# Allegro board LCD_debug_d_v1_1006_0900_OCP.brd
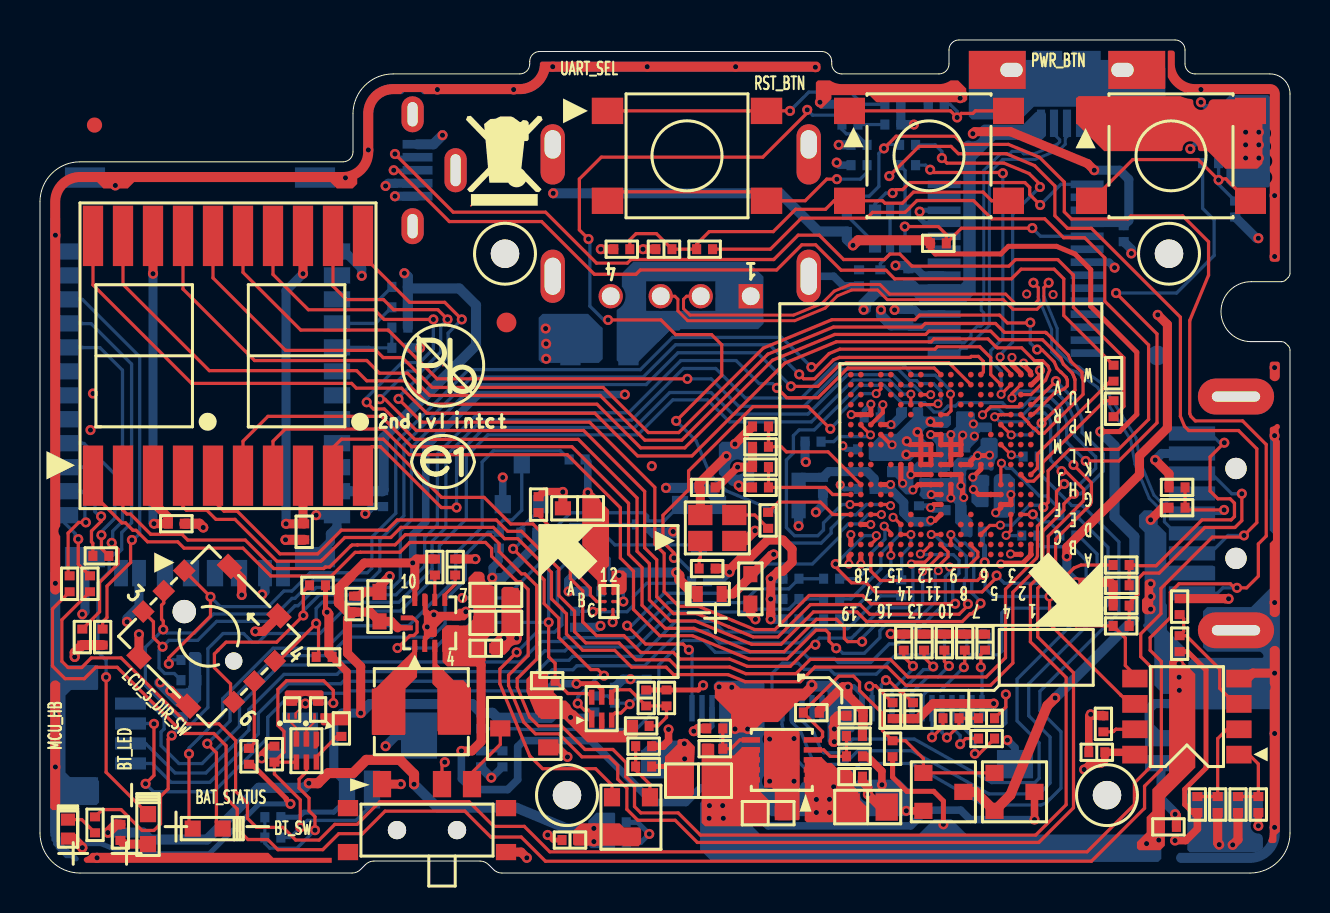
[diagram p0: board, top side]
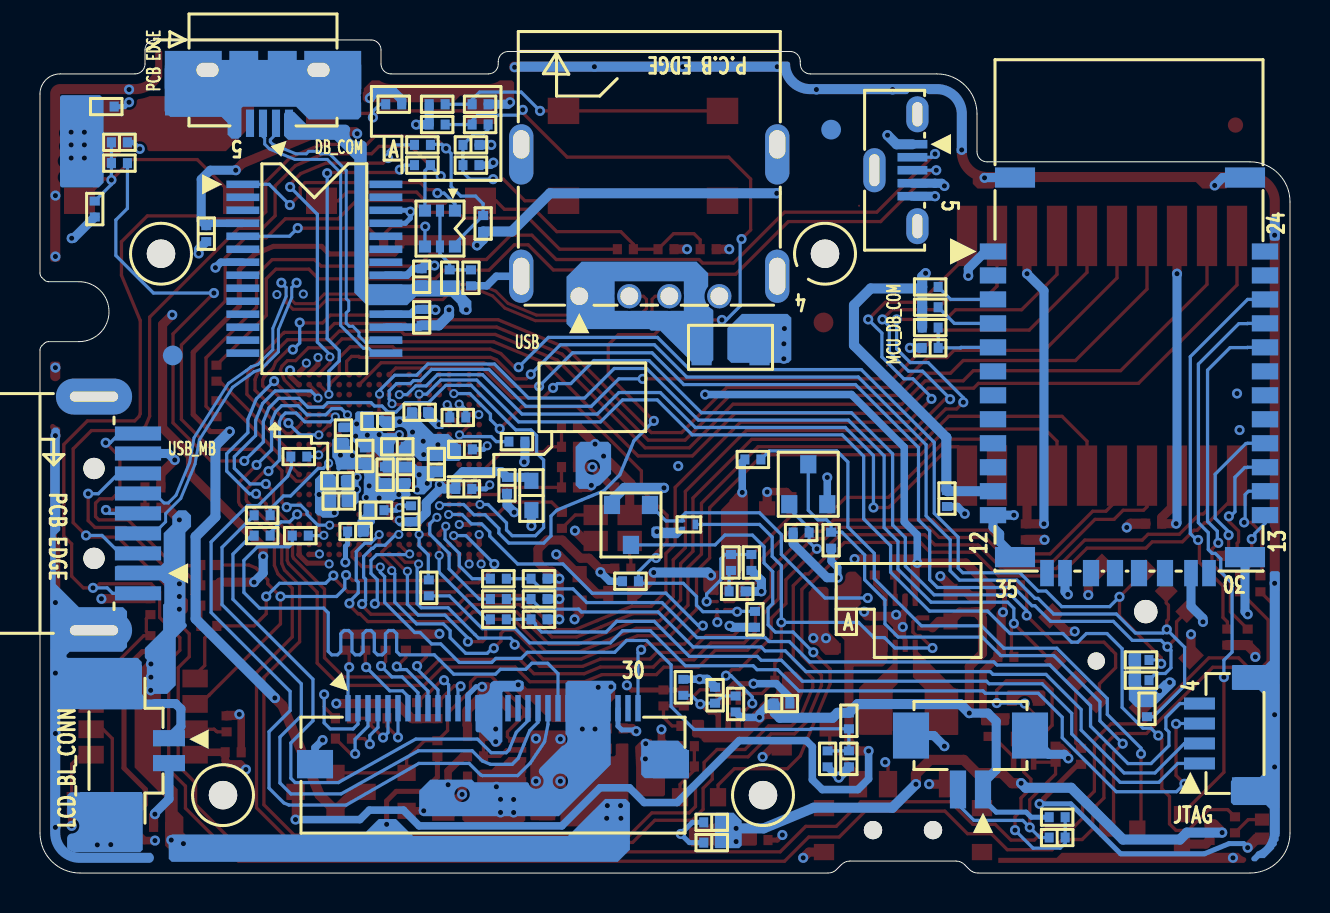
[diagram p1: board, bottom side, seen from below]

Outline 62.5 x 41.7 mm; copper layers: TOP, GND, VCC, BOTTOM. Coordinates in mm from the lower left corner of the outline.
Outline path: 0,33.6 0,2 arc(0.59,0.59) 2,0 15.6,0 arc(15.83,0.05) 16.03,0.18 16.27,0.42 arc(16.47,0.55) 16.7,0.6 22,0.6 arc(22.23,0.55) 22.43,0.42 22.67,0.18 arc(22.87,0.05) 23.1,0 60.5,0 arc(61.91,0.59) 62.5,2 62.5,26.18 arc(62.48,26.29) 62.41,26.39 62.29,26.51 arc(62.19,26.58) 62.08,26.6 60.55,26.6 arc(59.05,28.1) 60.55,29.6 62.08,29.6 arc(62.19,29.62) 62.29,29.69 62.41,29.81 arc(62.48,29.91) 62.5,30.02 62.5,39 arc(62.21,39.71) 61.5,40 57.75,40 arc(57.4,40.15) 57.25,40.5 57.25,41.2 arc(57.1,41.55) 56.75,41.7 45.95,41.7 arc(45.6,41.55) 45.45,41.2 45.45,40.5 arc(45.3,40.15) 44.95,40 40.09,40 arc(39.73,40.15) 39.59,40.5 39.59,40.62 arc(39.44,40.98) 39.09,41.12 24.99,41.12 arc(24.63,40.98) 24.49,40.62 24.49,40.5 arc(24.34,40.15) 23.99,40 17.65,40 arc(16.24,39.41) 15.65,38 15.65,36.1 arc(15.5,35.75) 15.15,35.6 2,35.6 arc(0.59,35.01) 0,33.6

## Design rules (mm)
net group BMC_UART_TX_R: nets BMC_UART_R_TX BMC_UART_TX_R
net group JTAG_TI_TDI: nets JTAG_TI_TDI JTAG_TI_TDI_R
net group BMC_UART_RX: nets BMC_UART_RX_R
net group JTAG_TI_TCK: nets JTAG_TI_TCK_R
net group JTAG_TI_TDO: nets JTAG_TI_TDO
net group JTAG_TI_TMS: nets JTAG_TI_TMS
net group SPI_BMC_LCD_CS_N: nets SPI_BMC_LCD_CS_N_R
net group SPI_BMC_LCD_SCK: nets SPI_BMC_LCD_SCK_R
net group SPI_BMC_LCD_SDI: nets SPI_BMC_LCD_SDI_R
net group SPI_BMC_LCD_SDO: nets SPI_BMC_LCD_SDO
net group UART: nets BMC_UART_RX_FT232
net group UART_TI_R_TXD: nets UART_TI_TXD
net group UART_TI_RXD: nets UART_TI_R_RXD
net group USB: nets USB2_DN USB2_DN_MICRO USB2_DP USB2_DP_MICRO
nets with their own width: min track width 0.254; nets P3V3_BIC P3V3_VOUT

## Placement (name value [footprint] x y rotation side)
BT1  SCONN2_DF13C-2P-1.25V(21)  [CON_2S1H2S_P1-25XC]  15.98 6.88 270 bottom
C4  0.1UF  [C0402]  17.15 18.75 90 bottom
C21  0.1UF  [C0402]  58.53 36.58 0 bottom
C65  0.1UF  [C0402]  33.36 19.3 0 top
C241  0.1UF  [C0402]  43.42 27.81 270 bottom
C242  0.1UF  [C0402]  54.19 32 90 bottom
C243  0.1UF  [C0402]  43.42 29.84 270 bottom
C244  0.1UF  [C0402]  31.2 31.23 0 top
C252  0.1UF  [C0402]  17.99 26.29 0 bottom
C254  0.1UF  [C0402]  40.72 4.83 0 top
C255  10UF  [C0805_H61]  41.38 3.3 0 top
C256  1UF  [C0603]  36.41 3 0 top
C257  10UF  [C0805_H61]  32.93 4.62 180 top
C258  0.01UF  [C0402]  43.95 17.98 90 bottom
C259  1UF  [C0402]  39.15 19.41 270 bottom
C272  0.01UF  [C0402]  44.23 19.94 90 bottom
C273  0.1UF  [C0402]  45.7 18.16 180 bottom
C275  1UF  [C0402]  45.25 19.94 90 bottom
C276  0.01UF  [C0402]  42.68 20.47 270 bottom
C278  0.1UF  [C0402]  44.64 21.34 0 bottom
C279  1UF  [C0402]  41.28 21.21 180 bottom
C280  1UF  [C0402]  45.63 22.61 0 bottom
C289  0.1UF  [C0402]  52.84 6.05 180 top
C290  1UF  [C0402]  46.24 11.56 90 top
C291  1UF  [C0402]  44.2 11.56 90 top
C292  1UF  [C0402]  45.22 11.56 90 top
C293  1UF  [C0402]  43.19 11.56 90 top
C294  1UF  [C0402]  43.65 8.13 270 top
C295  1UF  [C0402]  47.33 7.75 180 top
C296  1UF  [C0402]  47.33 6.73 0 top
C297  1UF  [C0402]  45.55 7.75 0 top
C298  1UF  [C0402]  47.25 11.56 90 top
C299  0.1UF  [C0402]  42.63 8.13 270 top
C300  0.1UF  [C0402]  40.75 7.87 0 top
C301  0.1UF  [C0402]  26.5 1.65 180 top
C302  10UF  [C0402]  28.91 2.54 0 bottom
C308  22UF  [C0402]  28.91 1.52 0 bottom
C315  1UF  [C0402]  43.52 23.06 180 bottom
C316  0.1UF  [C0402]  47.33 21.89 90 bottom
C317  0.01UF  [C0402]  41.61 22.8 180 bottom
C318  0.1UF  [C0402]  47.63 19.63 180 bottom
C319  0.1UF  [C0402]  46.26 20.88 90 bottom
C320  0.1UF  [C0402]  46.72 17.09 0 bottom
C321  0.1UF  [C0402]  47.56 18.62 180 bottom
C322  0.1UF  [C0402]  41.31 19.23 180 bottom
C323  2.2UF  [C0603]  37.93 18.9 270 bottom
C327  1UF  [C0603]  35.52 14.22 270 top
C329  0.01UF  [C0402]  27.64 14.1 180 bottom
C330  1UF  [C0603]  26.88 18.25 180 top
C331  0.1UF  [C0402]  25.41 8.48 180 bottom
C332  0.1UF  [C0402]  40.95 36.45 0 bottom
C333  0.1UF  [C0402]  22.06 5.71 270 bottom
C334  0.1UF  [C0402]  28.75 8.9 90 bottom
C335  0.1UF  [C0402]  30.31 8.76 90 top
C336  0.1UF  [C0402]  11.64 1.78 0 bottom
CN1  SCONN5_105133-0011  [USB1XAY]  19.77 35.18 270 bottom
D3  LED_GREEN  [LED_1921]  5.4 2.2 90 top
D6  7 seg LED RED  [LED20S_LTD-3813CKD-P]  9.4 25.89 90 top
D13  LED GREEN  [LED2S_0402]  1.4 2.2 90 top
D15  LED_SMD_RED  [LED_1921]  8.38 2.23 0 top
D16  RB161SS-20T2R  [D0603_RB161SS-20T2R]  33.49 13.97 180 top
D17  RB495DT146  [SOT346_0-95_2-9X1-6]  24.21 7.24 180 top
DM8  -  [WEEE]  21.55 33.4 0 top
DM9  -  [PB-E1_SMALL]  20.15 25.4 0 top
FS2  1.1A/8V  [F1206]  27.97 26.31 180 bottom
H2  -  [HOLE_D1-4N]  56.45 31 0 top
H3  -  [HOLE_D1-4N]  23.25 31 0 top
H4  -  [HOLE_D1-4N]  26.35 3.9 0 top
H5  -  [HOLE_D1-4N]  53.35 3.9 0 top
J1  CONN4_2UB4022-001131F  [USB1XBE]  35.54 28.87 0 bottom
J2  SCONN5_2UB1000000201F  [USB1XAK]  51.35 40.2 270 bottom
J4  SCONN30_50501-03001-001  [CON_30S1H2S_P0-5XC]  39.85 4.9 90 bottom
J5  SCONN2_50273-0020N-V09  [CON_2S1H2S_P1-25XA]  58.2 6.12 180 bottom
J13  SCONN4_50228-0047N-001  [CON_4S1H2S_P1XA]  2.75 6.99 0 bottom
NOREF  -  []  18.44 32.21 0 top
NOREF#2  -  []  287.74 15.11 0 top
NOREF#3  -  []  226.4 15.11 0 top
NOREF#4  -  []  354.71 16.31 0 top
NOREF#5  -  []  60.5 0 90 top
NOREF#6  -  []  241.77 0.25 0 top
NOREF#7  -  []  355.94 79.12 0 top
NOREF#8  -  []  60.79 13.46 0 top
NOREF#9  -  []  38.38 29.47 0 top
NOREF#10  -  []  -25 51 0 top
NOREF#11  -  []  0 0 0 top
NOREF#12  -  []  165 -143.25 90 top
NOREF#13  -  []  17.86 38.1 0 top
NOREF#14  -  []  0 0 0 top
NOREF#15  -  []  0 33.6 0 top
NOREF#16  -  []  -17 -143.25 0 top
NOREF#17  -  []  289.13 78.89 0 top
NOREF#18  -  []  48.7 40.74 0 top
NOREF#19  -  []  159 53 0 top
NOREF#20  -  []  25.46 29.51 0 top
NOREF#21  -  []  20.55 35.29 0 top
NOREF#22  -  []  60.66 22.61 0 top
NOREF#23  -  [unnamed#2]  23.33 27.56 0 top
NOREF#24  -  []  159 -143.25 0 top
NOREF#25  -  []  -53 245.11 0 top
NOREF#26  -  []  25.72 36.87 0 top
NOREF#27  -  []  -17 53 0 top
NOREF#28  -  []  54.68 40.27 0 top
NOREF#29  -  []  225.68 80.21 0 top
NOREF#30  -  []  38.14 36.75 0 top
NOREF#31  -  [unnamed#2]  55.86 25.91 180 bottom
NOREF#32  -  [unnamed#2]  22.94 37.21 180 bottom
OSC1  25MHZ  [OSC4_FJ2500009]  33.87 17.27 90 top
PC1  10UF  [C0603]  16.98 13.34 90 top
PC2  0.1UF  [C0402]  15.71 13.46 90 top
PC3  1000PF  [C0402]  20.76 15.32 90 top
PC6  0.1UF  [C0402]  22.28 11.25 0 top
PC7  10UF  [C0603]  22.79 12.52 0 top
PC8  10UF  [C0603]  22.79 13.92 0 top
PL1  1.5UH  [L_MMD-04BZ-1R5M-X2]  19.07 8.08 0 top
PR38  47K  [R0402]  19.74 15.32 270 top
PU1  TPS63051RMWR  [VQFN12_0-5_2-5X2-5]  19.49 12.52 90 top
Q5  NX7002AKS  [SOT363XB]  42.5 32.26 270 bottom
Q13  DMG3415U-7  [SOT23_GDSXC]  48.73 4.06 0 top
Q14  DMG6968U-7  [SOT23_GDSXC]  45.17 4.06 0 top
Q21  DMG3415U-7  [SOT23_GDSXC]  29.55 2.79 270 top
Q26  DMG6968U-7  [SOT23_GDSXC]  24.09 19.46 90 bottom
Q29  CSD17484F4  [PICOSTAR_GDS]  12.61 8.19 90 top
Q30  CSD17484F4  [PICOSTAR_GDS]  13.9 8.19 90 top
Q31  DMG3415U-7  [SOT23_GDSXC]  32.95 17.42 270 bottom
Q32  CSD17484F4  [PICOSTAR_GDS]  30.06 17.45 180 bottom
R1  0  [R0402]  1.48 14.48 90 top
R2  4.7K  [R0402]  2.12 11.81 90 top
R10  4.7K  [R0402]  17.99 28.32 180 bottom
R11  4.7K  [R0402]  17.99 29.34 180 bottom
R12  220  [R0402]  4.02 2.03 90 top
R13  1K  [R0402]  2.5 14.48 90 top
R44  0  [R0402]  36.41 17.65 90 top
R51  10K  [R0402]  33.36 15.24 180 top
R54  0  [R0402]  43.38 36.45 0 bottom
R72  0  [R0402]  49.56 20.85 0 bottom
R76  2.7K  [R0402]  59.19 38.37 0 bottom
R78  200  [R0402]  58.53 35.53 180 bottom
R79  33.2  [R0402]  51.39 16.89 0 bottom
R357  1.69K  [R0402]  42.02 29.79 90 bottom
R358  3.3K  [R0402]  40.95 29.79 270 bottom
R359  4.7K  [R0402]  40.34 32.51 90 bottom
R360  4.7K  [R0402]  44.92 31.52 0 top
R469  0  [R0402]  39.58 14.73 0 bottom
R471  10K  [R0402]  37.55 14.73 180 bottom
R473  0  [R0402]  43.06 14.27 90 bottom
R474  0  [R0402]  39.58 13.72 0 bottom
R475  10K  [R0402]  37.55 13.72 180 bottom
R512  220  [R0402]  2.75 2.41 270 top
R513  33.2  [R0402]  51.39 17.91 0 bottom
R516  33.2  [R0402]  49.49 16.89 0 bottom
R724  2.7K  [R0402]  44.81 38.48 0 bottom
R725  200  [R0402]  33.23 31.23 0 top
R730  4.7K  [R0402]  17.99 27.3 180 bottom
R731  0  [R0402]  3.04 15.88 0 top
R732  4.7K  [R0402]  3.13 11.81 90 top
R742  11.5K  [R0402]  40.72 6.86 0 top
R743  36K  [R0402]  40.72 5.84 180 top
R757  220  [R0402]  56.42 2.31 180 top
R758  300  [R0402]  6.82 17.49 0 top
R759  300  [R0402]  13.21 17.08 270 top
R762  47K  [R0402]  33.74 6.22 0 top
R786  4.7K  [R0402]  56.98 11.48 90 top
R787  4.7K  [R0402]  57.87 3.43 90 top
R788  4.7K  [R0402]  60.92 3.43 90 top
R789  4.7K  [R0402]  53.17 7.47 90 top
R790  1K  [R0402]  59.9 3.43 90 top
R791  1K  [R0402]  58.89 3.43 90 top
R792  1K  [R0402]  56.98 13.34 90 top
R808  49.9K  [R0402]  38.57 8.03 0 top
R864  17.8K  [R0402]  33.74 7.24 180 top
R865  16K  [R0402]  31.33 8.76 90 top
R870  0  [R0402]  53.68 23.24 270 top
R871  0  [R0402]  53.68 25.02 90 top
R873  0  [R0402]  43.38 35.43 0 bottom
R875  4.7K  [R0402]  38.65 21.6 0 bottom
R880  4.7K  [R0402]  40.95 35.43 0 bottom
R881  0  [R0402]  39.58 12.7 0 bottom
R882  10K  [R0402]  37.55 12.7 180 bottom
R888  0  [R0402]  40.5 37.47 0 bottom
R893  3.83K  [R0402]  26.93 15.54 270 bottom
R894  6.04K  [R0402]  26.75 12.7 270 bottom
R895  2.7K  [R0402]  27.95 15.54 270 bottom
R896  10K  [R0402]  24.93 18.44 90 top
R898  113K  [R0402]  30.06 7.37 0 top
R900  10K  [R0402]  56.85 19.3 0 top
R901  10K  [R0402]  56.85 18.29 180 top
R902  10K  [R0402]  22.94 16.66 90 bottom
R903  4.99K  [R0402]  42.63 6.22 270 top
R905  10K  [R0402]  30.18 5.33 0 top
R906  0  [R0402]  30.18 6.35 0 top
R907  100K  [R0402]  25.36 9.63 0 top
R910  49.9K  [R0402]  29.09 31.23 180 top
R911  2.7K  [R0402]  40.5 38.48 0 bottom
R912  49.9K  [R0402]  42.64 37.47 0 bottom
R913  0  [R0402]  42.64 38.48 0 bottom
R914  49.9K  [R0402]  7.45 9.65 0 bottom
R915  49.9K  [R0402]  13.88 14.4 0 top
R916  49.9K  [R0402]  7.15 8.22 90 bottom
R917  49.9K  [R0402]  7.45 10.67 0 bottom
R918  49.9K  [R0402]  14.21 10.82 0 top
R919  2.7K  [R0402]  10.45 5.84 90 top
R920  1K  [R0402]  36.03 19.3 180 top
R921  10K  [R0402]  36.03 20.32 0 top
R922  1K  [R0402]  36.03 22.35 180 top
R923  10K  [R0402]  36.03 21.34 0 top
R924  4.7K  [R0402]  54.06 13.39 0 top
R925  4.7K  [R0402]  54.06 14.4 0 top
R926  0  [R0402]  54.06 15.42 180 top
R927  0  [R0402]  54.06 12.37 180 top
R928  41.2K  [R0402]  22.06 7.62 270 bottom
R929  8.25K  [R0402]  23.12 5.71 270 bottom
R930  220  [R0402]  26.86 20.7 0 bottom
R933  12.1K  [R0402]  30.34 9.3 90 bottom
R934  88.7K  [R0402]  27.72 8.46 90 bottom
R935  100K  [R0402]  24.44 17.04 180 bottom
R936  4.7K  [R0402]  32.98 14.61 180 bottom
R941  330  [R0402]  11.64 2.79 0 bottom
R942  2.2K  [R0402]  15.07 7.24 270 top
R943  0  [R0402]  11.72 5.95 270 top
R944  49.9K  [R0402]  59.76 33.24 270 bottom
S1  SW4S_DTSM-65R-Q-T/R  [SW4S_DTSM-65N]  56.55 35.9 90 top
S2  SW4S_DTSM-65K-Q-T/R  [SW4S_DTSM-65N]  44.45 35.9 90 top
S3  -  [SW_RST-1202]  19.35 2.15 90 top
SW5  DTSM-65N-S-Q-TR  [SW_DTSM-62N-S-V-TR]  32.35 35.9 0 top
SW6  -  [SW6S_HSS177]  8.45 11.85 315 top
TP7  TP_BOM  [TP30]  2.73 37.44 0 top
U5  FT232RL-REEL  [SSOP28_0-65_10-2X5-3]  48.78 30.25 180 bottom
U10  MODULE_RN42-I/RM  [BLUETOOTH35S]  8.05 27.91 180 bottom
U12  RT9059GQW  [DFN10_THXE]  37.09 5.66 180 top
U15  SCONN9_2UP1000-000111F  [USB1XBF]  68.15 18 270 bottom
U16  M24128-BWMN6TP  [SOIC8XH]  57.35 7.83 180 top
U21  TM4C1290NCZADI3R  [BGA212]  45.04 20.45 180 top
U22  BQ25101YFPT  [DSBGA6_0-4_0-88X1-58]  28.45 13.59 0 top
U23  TPS3700DSER  [WSON6_0-5_1-5X1-5]  28.09 8.23 90 top
U24  BQ29700DSER  [WSON6_0-5_1-5X1-5XA]  13.32 6.13 270 top

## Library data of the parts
BT1 J5 = SCONN2_502730020N001
C4 C21 C65 C241-C244 C252 C254-C259 C272 C273 C275 C276 C278-C280 C289-C302 C308 C315-C323 C327 C329-C336 PC1-PC3 PC6-PC8 = CAP_NP
CN1 = SCONN5_1051330011
D3 D13 D15 = LED_0
D6 = LED20S_LTD3813CKDP
D16 = MBRS340_0
D17 = RB495DT146
DM8 DM9 = DUMMY_SYMBOL
FS2 = FUSE
H2-H5 = HOLE_N
J1 = CONN4_2UB4022001131F
J2 = SCONN5_2UB1000000201F
J4 = SCONN30_5050103001001
J13 = SCONN4_502280047N001
OSC1 = OSC-4
PL1 = L
PR38 R2 R10-R12 R44 R51 R76 R78 R357-R360 R471 R475 R512 R724 R725 R730-R732 R742 R743 R757-R759 R762 R786-R792 R808 R864 R865 R875 R880 R882 R888 R893-R896 R898 R900-R903 R905-R907 R910-R930 R933-R936 R941-R944 = R
PU1 = TPS63051RMWR
Q5 = MOSFET_DUAL_6P
Q13 Q21 Q31 = MOSFET_PCH_GDS
Q14 Q26 Q29 Q30 Q32 = MOSFET_N_GSD
R1 R54 R72 R469 R473 R474 R870 R871 R873 R881 = R: signal model: R_R0402_DISCRETE_0_0
R13 = R: signal model: R_R0402_DISCRETE_1K_1K
R79 R513 R516 = R: signal model: R_R0402_DISCRETE_33.2_33.2
S1 SW5 = SW_PUSHBUTTON4P_24
S2 = SW_PUSHBUTTON4P_1-3
S3 = RST-1202
SW6 = SW6S_HSS177
TP7 = TP
U5 = FT232RLREEL
U10 = MODULE_RN42IRM
U12 = RT9059GQW
U15 = SCONN9_2UP1000000111F
U16 = M24128
U21 = TM4C1290NCZADI3R
U22 = BQ25101YFPT
U23 = TPS3700DSER
U24 = BQ29700DSER

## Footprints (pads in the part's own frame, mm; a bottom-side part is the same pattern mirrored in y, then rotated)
BGA212
  round 0.292 smd: A1(-4.5,4.5) A2(-4,4.5) A4(-3,4.5) A5(-2.5,4.5) A7(-1.5,4.5) A8(-1,4.5) A10(0,4.5) A11(0.5,4.5) A13(1.5,4.5) A14(2,4.5) A16(3,4.5) A17(3.5,4.5) A18(4,4.5) A19(4.5,4.5) B1(-4.5,4) B2(-4,4) B3(-3.5,4) B4(-3,4) B5(-2.5,4) B6(-2,4) B7(-1.5,4) B8(-1,4) B9(-0.5,4) B10(0,4) B11(0.5,4) B12(1,4) B13(1.5,4) B14(2,4) B15(2.5,4) B16(3,4) B17(3.5,4) B18(4,4) B19(4.5,4) C1(-4.5,3.5) C2(-4,3.5) C5(-2.5,3.5) C6(-2,3.5) C8(-1,3.5) C10(0,3.5) C12(1,3.5) C14(2,3.5) C15(2.5,3.5) C18(4,3.5) D1(-4.5,3) D2(-4,3) D6(-2,3) D7(-1.5,3) D8(-1,3) D12(1,3) D13(1.5,3) D14(2,3) D18(4,3) D19(4.5,3) E2(-4,2.5) E3(-3.5,2.5) E7(-1.5,2.5) E10(0,2.5) E13(1.5,2.5) E17(3.5,2.5) E18(4,2.5) E19(4.5,2.5) F1(-4.5,2) F2(-4,2) F3(-3.5,2) F4(-3,2) F10(0,2) F16(3,2) F17(3.5,2) F18(4,2) G1(-4.5,1.5) G2(-4,1.5) G4(-3,1.5) G5(-2.5,1.5) G10(0,1.5) G15(2.5,1.5) G16(3,1.5) G18(4,1.5) G19(4.5,1.5) H2(-4,1) H3(-3.5,1) H4(-3,1) H9(-0.5,1) H10(0,1) H11(0.5,1) H12(1,1) H16(3,1) H17(3.5,1) H18(4,1) H19(4.5,1) J1(-4.5,0.5) J2(-4,0.5) J8(-1,0.5) J9(-0.5,0.5) J10(0,0.5) J11(0.5,0.5) J12(1,0.5) J18(4,0.5) K1(-4.5,0) K2(-4,0) K3(-3.5,0) K5(-2.5,0) K6(-2,0) K7(-1.5,0) K8(-1,0) K9(-0.5,0) K10(0,0) K11(0.5,0) K12(1,0) K13(1.5,0) K14(2,0) K15(2.5,0) K17(3.5,0) K18(4,0) K19(4.5,0) L2(-4,-0.5) L8(-1,-0.5) L9(-0.5,-0.5) L10(0,-0.5) L11(0.5,-0.5) L12(1,-0.5) L18(4,-0.5) L19(4.5,-0.5) M1(-4.5,-1) M2(-4,-1) M3(-3.5,-1) M4(-3,-1) M8(-1,-1) M9(-0.5,-1) M10(0,-1) M11(0.5,-1) M12(1,-1) M16(3,-1) M17(3.5,-1) M18(4,-1) N1(-4.5,-1.5) N2(-4,-1.5) N4(-3,-1.5) N5(-2.5,-1.5) N10(0,-1.5) N15(2.5,-1.5) N16(3,-1.5) N18(4,-1.5) N19(4.5,-1.5) P2(-4,-2) P3(-3.5,-2) P4(-3,-2) P10(0,-2) P16(3,-2) P17(3.5,-2) P18(4,-2) P19(4.5,-2) R1(-4.5,-2.5) R2(-4,-2.5) R3(-3.5,-2.5) R7(-1.5,-2.5) R10(0,-2.5) R13(1.5,-2.5) R17(3.5,-2.5) R18(4,-2.5) T1(-4.5,-3) T2(-4,-3) T6(-2,-3) T7(-1.5,-3) T8(-1,-3) T12(1,-3) T13(1.5,-3) T14(2,-3) T18(4,-3) T19(4.5,-3) U2(-4,-3.5) U5(-2.5,-3.5) U6(-2,-3.5) U8(-1,-3.5) U10(0,-3.5) U12(1,-3.5) U14(2,-3.5) U15(2.5,-3.5) U18(4,-3.5) U19(4.5,-3.5) V1(-4.5,-4) V2(-4,-4) V3(-3.5,-4) V4(-3,-4) V5(-2.5,-4) V6(-2,-4) V7(-1.5,-4) V8(-1,-4) V9(-0.5,-4) V10(0,-4) V11(0.5,-4) V12(1,-4) V13(1.5,-4) V14(2,-4) V15(2.5,-4) V16(3,-4) V17(3.5,-4) V18(4,-4) V19(4.5,-4) W1(-4.5,-4.5) W2(-4,-4.5) W3(-3.5,-4.5) W4(-3,-4.5) W6(-2,-4.5) W7(-1.5,-4.5) W9(-0.5,-4.5) W10(0,-4.5) W12(1,-4.5) W13(1.5,-4.5) W15(2.5,-4.5) W16(3,-4.5) W18(4,-4.5) W19(4.5,-4.5)
BLUETOOTH35S
  rect 1.321x0.813 smd: 1(-6.8,3.2) 2(-6.8,2) 3(-6.8,0.8) 4(-6.8,-0.4) 5(-6.8,-1.6) 6(-6.8,-2.8) 7(-6.8,-4) 8(-6.8,-5.2) 9(-6.8,-6.4) 10(-6.8,-7.6) 11(-6.8,-8.8) 12(-6.8,-10) 13(6.8,-10) 14(6.8,-8.8) 15(6.8,-7.6) 16(6.8,-6.4) 17(6.8,-5.2) 18(6.8,-4) 19(6.8,-2.8) 20(6.8,-1.6) 21(6.8,-0.4) 22(6.8,0.8) 23(6.8,2) 24(6.8,3.2)
  rect 0.686x1.321 smd: 28(3.1,-12.9) 29(-3.2,-12.9) 30(4,-12.9) 35(-4.1,-12.9)
  rect 0.813x1.321 smd: 31(1.8,-12.9) 32(0.5,-12.9) 33(-0.7,-12.9) 34(-1.9,-12.9)
  rect 2.007x1.016 smd: G1(-5.7,6.9) G2(5.8,6.9) G3(-5.7,-12.1) G4(5.8,-12.1)
C0402
  rect 0.457x0.508 smd: 1(-0.4,0) 2(0.4,0)
C0603
  rect 0.813x0.711 smd: 1(-0.737,0) 2(0.737,0)
C0805_H61
  rect 1.118x1.372 smd: 1(-0.95,0) 2(0.95,0)
CON_2S1H2S_P1-25XA
  rect 1.6x0.813 smd: 1(2.15,0.625) 2(2.15,-0.625)
  rect 3.099x2.21 smd: G1(-0.75,3.175) G2(-0.75,-3.175)
CON_2S1H2S_P1-25XC
  rect 1.905x0.813 smd: 1(2.7,0.625) 2(2.7,-0.625)
  rect 2.311x1.803 smd: G1(0,2.975) G2(0,-2.975)
CON_4S1H2S_P1XA
  rect 1.549x0.61 smd: 1(1.775,1.5) 2(1.775,0.5) 3(1.775,-0.5) 4(1.775,-1.5)
  rect 1.803x1.219 smd: G1(-0.75,-2.8) G2(-0.75,2.8)
CON_30S1H2S_P0-5XC
  rect 1.321x0.279 smd: 1(3.35,7.25) 2(3.35,6.75) 3(3.35,6.25) 4(3.35,5.75) 5(3.35,5.25) 6(3.35,4.75) 7(3.35,4.25) 8(3.35,3.75) 9(3.35,3.25) 10(3.35,2.75) 11(3.35,2.25) 12(3.35,1.75) 13(3.35,1.25) 14(3.35,0.75) 15(3.35,0.25) 16(3.35,-0.25) 17(3.35,-0.75) 18(3.35,-1.25) 19(3.35,-1.75) 20(3.35,-2.25) 21(3.35,-2.75) 22(3.35,-3.25) 23(3.35,-3.75) 24(3.35,-4.25) 25(3.35,-4.75) 26(3.35,-5.25) 27(3.35,-5.75) 28(3.35,-6.25) 29(3.35,-6.75) 30(3.35,-7.25)
  rect 1.422x1.803 smd: G1(0.55,8.9) G2(0.55,-8.9)
D0603_RB161SS-20T2R
  rect 0.508x0.813 smd: A(-0.6,0) C(0.6,0)
DFN10_THXE
  rect 0.914x0.279 smd: 1(-1.55,1) 2(-1.55,0.5) 3(-1.55,0) 4(-1.55,-0.5) 5(-1.55,-1) 6(1.55,-1) 7(1.55,-0.5) 8(1.55,0) 9(1.55,0.5) 10(1.55,1)
  rect 1.753x2.667 smd: TH(0,0)
DSBGA6_0-4_0-88X1-58
  round 0.178 smd: A1(-0.2,0.4) A2(0.2,0.4) B1(-0.2,0) B2(0.2,0) C1(-0.2,-0.4) C2(0.2,-0.4)
F1206
  rect 1.016x1.803 smd: 1(-1.45,0) 2(1.45,0)
HOLE_D1-4N
  round 1.422 hole 1.422 unplated: (0,0)
L_MMD-04BZ-1R5M-X2
  rect 1.651x2.311 smd: 1(-1.65,0) 2(1.65,0)
LED2S_0402
  rect 0.61x0.711 smd: A(-0.475,0) C(0.475,0)
LED20S_LTD-3813CKD-P
  rect 3.023x1.016 smd: 1(-6,6.75) 2(-6,5.25) 3(-6,3.75) 4(-6,2.25) 5(-6,0.75) 6(-6,-0.75) 7(-6,-2.25) 8(-6,-3.75) 9(-6,-5.25) 10(-6,-6.75) 11(6,-6.75) 12(6,-5.25) 13(6,-3.75) 14(6,-2.25) 15(6,-0.75) 16(6,0.75) 17(6,2.25) 18(6,3.75) 19(6,5.25) 20(6,6.75)
LED_1921
  rect 0.813x0.813 smd: A(-0.75,0) C(0.75,0)
OSC4_FJ2500009
  rect 1.016x1.219 smd: 1(-0.65,0.85) 2(-0.65,-0.85) 3(0.65,-0.85) 4(0.65,0.85)
PB-E1_SMALL
  round 0.102 smd: 1(0,0)
PICOSTAR_GDS
  rect 0.279x0.508 smd: D(0.325,0)
  rect 0.279x0.127 smd: G(-0.325,0.175) S(-0.325,-0.175)
R0402
  rect 0.457x0.508 smd: 1(-0.4,0) 2(0.4,0)
SOIC8XH
  rect 1.27x0.889 smd: 1(-2.6,1.905) 2(-2.6,0.635) 3(-2.6,-0.635) 4(-2.6,-1.905) 5(2.6,-1.905) 6(2.6,-0.635) 7(2.6,0.635) 8(2.6,1.905)
SOT23_GDSXC
  rect 0.914x0.813 smd: D(1,0) G(-1,0.95) S(-1,-0.95)
SOT346_0-95_2-9X1-6
  rect 1.016x0.813 smd: 1(-1.2,-0.95) 2(-1.2,0.95) 3(1.2,0)
SOT363XB
  rect 0.61x0.61 smd: 1(-0.9,0.75) 3(-0.9,-0.75) 4(0.9,-0.75) 6(0.9,0.75)
  rect 0.61x0.406 smd: 2(-0.9,0) 5(0.9,0)
SSOP28_0-65_10-2X5-3
  rect 1.651x0.381 smd: 1(-3.575,4.225) 2(-3.575,3.575) 3(-3.575,2.925) 4(-3.575,2.275) 5(-3.575,1.625) 6(-3.575,0.975) 7(-3.575,0.325) 8(-3.575,-0.325) 9(-3.575,-0.975) 10(-3.575,-1.625) 11(-3.575,-2.275) 12(-3.575,-2.925) 13(-3.575,-3.575) 14(-3.575,-4.225) 15(3.575,-4.225) 16(3.575,-3.575) 17(3.575,-2.925) 18(3.575,-2.275) 19(3.575,-1.625) 20(3.575,-0.975) 21(3.575,-0.325) 22(3.575,0.325) 23(3.575,0.975) 24(3.575,1.625) 25(3.575,2.275) 26(3.575,2.925) 27(3.575,3.575) 28(3.575,4.225)
SW4S_DTSM-65N
  rect 1.321x1.549 smd: 1(2.25,3.975) 2(2.25,-3.975) 3(-2.25,3.975) 4(-2.25,-3.975)
SW6S_HSS177
  round 1.168 hole 1.168 unplated: (-1.75,0)
  round 0.864 hole 0.864 unplated: (1.75,0)
  rect 0.813x0.813 smd: 1(-3.2,1.45) 2(-3.2,0) 3(-3.2,-1.45) 4(3.2,1.45) 5(3.2,0) 6(3.2,-1.45)
  rect 1.016x0.813 smd: G1(-1.75,3.2) G2(1.75,3.2) G3(-1.75,-3.2) G4(1.75,-3.2)
SW_DTSM-62N-S-V-TR
  rect 1.575x1.321 smd: 1(-3.975,2.25) 2(3.975,2.25) 3(-3.975,-2.25) 4(3.975,-2.25)
SW_RST-1202
  round 0.914 hole 0.914 unplated: (0,1.5) (0,-1.5)
  rect 1.321x0.914 smd: 1(2.3,2.25) 2(2.3,-0.75) 3(2.3,-2.25)
  rect 0.813x1.016 smd: 4(1.1,3.95) 5(1.1,-3.95) 6(-1.1,3.95) 7(-1.1,-3.95)
TP30
  round 0.762 smd: 1(0,0)
unnamed#2
  round 0.991 smd: 1(0,0)
USB1XAK
  rect 1.372x0.406 smd: 1(2.67,1.3) 2(2.67,0.65) 3(2.67,0) 4(2.67,-0.65) 5(2.67,-1.3)
  custom 0.25x0.25 smd: G1(1.78,-3.487) G6(1.78,3.487)
  rect 1.905x2.845 hole 0.711x1.118: G2(0,-2.775) G5(0,2.775)
  rect 1.905x1.448 smd: G3(0,-0.962) G4(0,0.962)
USB1XAY
  rect 0.432x1.499 smd: 1(-1.3,0.89) 2(-0.65,0.89) 3(0,0.89) 4(0.65,0.89) 5(1.3,0.89)
  oval 1.803x1.118 hole 1.219x0.508: G1(-2.8,1.14) G2(2.8,1.14)
  oval 2.21x1.118 hole 1.6x0.508: G3(0,-1.01)
USB1XBE
  rect 1.219x1.219 hole 0.889: 1(0,0)
  round 1.219 hole 0.889: 2(-2.5,0) 3(-4.5,0) 4(-7,0)
  oval 1.219x2.667 hole 0.813x1.854: G1(2.9,-1) G2(-9.9,-1)
  oval 1.219x3.023 hole 0.813x1.422: G3(2.9,-7.6) G4(-9.9,-7.6)
USB1XBF
  round 1.067 hole 1.067 unplated: (-2.25,8.35) (2.25,8.35)
  rect 0.711x2.311 smd: 1(3,10.55) 2(1,10.55) 3(-1,10.55) 4(-3,10.55) 5(-4,10.55) 6(-2,10.55) 7(0,10.55) 8(2,10.55) 9(4,10.55)
  oval 1.803x3.81 hole 0.508x2.413: G1(5.85,8.35) G2(-5.85,8.35)
VQFN12_0-5_2-5X2-5
  rect 0.61x0.254 smd: 1(-1.15,0.75) 2(-1.15,0.25) 3(-1.15,-0.25) 4(-1.15,-0.75) 7(1.15,-0.75) 8(1.15,-0.25) 9(1.15,0.25) 10(1.15,0.75)
  rect 0.254x0.61 smd: 5(-0.25,-1.15) 6(0.25,-1.15) 11(0.25,1.15) 12(-0.25,1.15)
WEEE
  round 0.102 smd: 1(0,0)
WSON6_0-5_1-5X1-5
  rect 0.864x0.279 smd: 1(-0.525,0.5)
  rect 0.762x0.279 smd: 2(-0.575,0) 3(-0.575,-0.5) 4(0.575,-0.5) 5(0.575,0) 6(0.575,0.5)
WSON6_0-5_1-5X1-5XA
  custom 0.07x0.07 smd: 1(-0.525,0.5)
  rect 0.762x0.279 smd: 2(-0.575,0) 3(-0.575,-0.5) 4(0.575,-0.5) 5(0.575,0) 6(0.575,0.5)

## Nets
GND: BT1.G1 BT1.G2 C4.1 C21.1 C65.2 C241.1 C242.1 C243.1 C244.1 C252.2 C254.2 C255.2 C256.2 C257.2 C258.2 C259.2 C272.2 C273.2 C275.2 C276.2 C278.2 C279.2 C280.2 C289.2 C290.2 C291.2 C292.2 C293.2 C294.2 C298.2 C299.2 C300.2 C301.2 C302.2 C308.2 C315.2 C316.2 C317.2 C318.2 C319.2 C320.2 C321.2 C322.2 C323.2 C327.2 C329.2 C330.2 C331.2 C332.1 C333.2 C334.2 C335.2 CN1.4(ID) CN1.5(GND) CN1.G1 CN1.G2 CN1.G3 J1.4(GND) J1.G1 J1.G2 J1.G3 J1.G4 J2.5(GND1) J2.G1(GND2) J2.G2(GND3) J2.G3(GND4) J2.G4(GND5) J2.G5(GND6) J2.G6(GND7) J4.13 J4.28 J4.G1 J4.G2 J5.1 J5.G1 J5.G2 J13.G1 J13.G2 OSC1.2(GND) PC1.2 PC2.2 PC3.2 PC6.2 PC7.2 PC8.2 PU1.2(GND1) PU1.6(PFM||PWM) PU1.9(GND2) Q26.S(SOURCE) Q30.S(SOURCE) Q32.S(SOURCE) R358.2 R742.2 R789.2 R790.1 R791.1 R792.2 R808.2 R864.2 R865.2 R893.2 R894.2 R896.2 R900.1 R905.2 R910.2 R912.2 R913.2 R914.2 R915.2 R916.2 R917.2 R918.2 R921.1 R923.1 R929.2 R933.2 R942.1 R943.1 R944.2 S3.1(A1) S3.7(G4) SW6.G1 SW6.G2 SW6.G3 SW6.G4 U5.7(GND0) U5.18(GND1) U5.21(GND2) U5.25(AGND) U5.26(TEST) U10.1(GND1) U10.12(GND2) U10.28(GND3) U10.29(GND4) U10.G1 U10.G2 U10.G3 U10.G4 U12.TH(EP) U15.4(GND) U15.G1 U15.G2 U16.4(VSS) U21.A1(GND_A1) U21.A2(GND_A2) U21.A18(GND_A18) U21.A19(GND_A19) U21.B1(GND_B1) U21.B19(GND_B19) U21.D18(GNDX2) U21.F10(GND_F10) U21.G4(GNDA) U21.G5(VREFA-) U21.H10(GND_H10) U21.H11(GND_H11) U21.H12(GND_H12) U21.J11(GND_J11) U21.J12(GND_J12) U21.K6(GND_K6) U21.K9(GND_K9) U21.K10(GND_K10) U21.K13(GND_K13) U21.K14(GND_K14) U21.L8(GND_L8) U21.L9(GND_L9) U21.M8(GND_M8) U21.M9(GND_M9) U21.M10(GND_M10) U21.N10(GND_N10) U21.P16(GND_P16) U21.R17(GND_R17) U21.R18(GNDX) U21.V1(GND_V1) U21.W1(GND_W1) U21.W2(GND_W2) U22.C2(VSS) U23.5(GND)
P3V3_ADJ: R742.1 R743.2 U12.4(ADJ)
P3V3_BAT: PC6.1 PC7.1 PC8.1 PU1.4(VOUT) PU1.5(FB) Q13.D
P3V3_BAT_EN: PU1.11(EN) Q32.D(DRAIN) R907.2 U23.6(OUTA)
P3V3_BIC: C65.1 C254.1 C255.1 C272.1 C273.1 C275.1 C276.1 C278.1 C279.1 C280.1 C289.1 C300.1 C315.1 C316.1 C317.1 C318.1 C319.1 C320.1 C321.1 D13.A D17.2 J4.14 J4.15 J4.16 J4.23 J4.24 J4.25 J4.26 J4.27 OSC1.4(VDD) Q14.S(SOURCE) R51.1 R76.1 R471.2 R475.2 R724.1 R743.1 R786.1 R787.1 R788.1 R875.1 R880.1 R882.2 R911.1 R919.1 R920.2 R922.2 R924.1 R925.1 R936.1 U12.1(VOUT1) U12.2(VOUT2) U12.3(VOUT3) U16.8(VCC) U21.F3(VDDA) U21.F4(VREFA+) U21.G10(VDD_G10) U21.H9(VDD_H9) U21.J8(VDD_J8) U21.J9(VDD_J9) U21.J10(VDD_J10) U21.K7(VDD_K7) U21.K8(VDD_K8) U21.K11(VDD_K11) U21.K12(VDD_K12) U21.L10(VDD_L10) U21.L11(VDD_L11) U21.L12(VDD_L12) U21.M11(VDD_M11) U21.M12(VDD_M12) U21.N16(VDD_N16) U21.P10(VDD_P10) U21.P17(VDD_P17)
P3V3_BT: C4.2 C301.1 C302.1 C308.1 Q21.D R2.1 R10.1 R11.1 R12.2 R730.1 R732.1 U10.11(VDD)
P3V3_BT_ON: Q21.S Q31.D
P3V3_EN: R762.2 R864.1 U12.6(EN)
P3V3_SW: Q13.S Q14.D(DRAIN) Q31.S R359.1 R360.1
P3V3_VOUT: C241.2 C242.2 U5.4(VCCIO) U5.17(3V3OUT)
P5V_MB: C256.1 C257.1 C327.1 CN1.1(VBUS) D16.A FS2.2 R757.2 R758.2 R759.2 R762.1 R901.2 R903.2 U12.7(VIN1) U12.8(VIN2) U12.9(VIN3) U12.10(VDD) U15.1(VBUS)
P5V_MB_FUSE: FS2.1 J1.1(VBUS)
P5V_MB_LCD: J5.2 R757.1
P5V_USB: C243.2 J2.1(VBUS) R357.1 R906.2 U5.19(RESET_N) U5.20(VCC)
VBAT: BT1.1 C330.1 C331.1 D17.1 PC1.1 PC2.1 PR38.1 PU1.10(ILIM0) PU1.12(VIN) R898.1 R902.1 R907.1 R928.1 R930.2 R934.1 R935.1 R941.2 U22.A1(OUT) U23.2(VDD)
VBAT_3.2V_TRIGGER: C335.1 R865.1 R898.2 U23.4(INA+)
VBAT_3.3V_LOW_LED: C334.1 R933.1 R934.2 U23.3(INB-)
VBAT_CHG_BLINK: U21.U19(PK4)
VBAT_LOW_LED: Q26.G(GATE) R935.2 U23.1(OUTB)
VBAT_LOW_LED_N: D15.C Q26.D(DRAIN) R902.2
VBAT_SCALED: C333.1 R928.2 R929.1 U21.B7(PE7_AIN21)
VDDC_OUTPUT: C258.1 C259.1 C322.1 C323.1 U21.E10(VDDC_E10) U21.H16(VDDC_H16)
BMC_HARTBEAT_LED_R: R512.1 U21.T13(PS5)
BMC_HEARTBEAT_LED: D13.C R512.2
BMC_RST_N: R875.2 U21.P18(RST#)
BMC_UART_R_RX: R54.2 U21.W3(PA1_U0TX)
BMC_UART_R_TX: R873.2 U21.V3(PA0_U0RX)
BMC_UART_RX: Q5.6(D1) R1.1 R54.1 R359.2 U15.9(SSTX+)
BMC_UART_RX_FT232: Q5.1(S1) U5.1(TXD)
BMC_UART_RX_R: R1.2 U10.14(UART_TX)
BMC_UART_TX: Q5.3(D2) R13.1 R873.1 U15.8(SSTX-)
BMC_UART_TX_FT232: Q5.4(S2) R360.2 U5.5(RXD)
BMC_UART_TX_R: R13.2 U10.13(UART_RX)
BQ25101_CHG_N: R894.1 R936.2 U21.V16(PK6) U22.C1(CHG#)
BQ25101_IN: D16.C U22.A2(IN)
BQ25101_ISET: R893.1 R895.1 U22.B2(ISET)
BQ25101_TS: R896.1 U22.B1(TS)
BT_STATUS_N: D3.C U10.21(GPIO5)
CELL_NEGATIVE: BT1.2 C336.2 Q29.S(SOURCE) R943.2 U24.4(VSS)
CHARGE_GATE: Q30.G(GATE) U24.2(COUT)
CLK_25M_MINIBMC_CLKIN: OSC1.3(OUT) R44.1
CLK_25M_MINIBMC_CLKIN_R: R44.2 U21.E19(OSC0)
DBCARD_INSERT_DET: U21.E7(PJ1)
DEBUG_V2_PRSNT: R900.2 R901.1 U15.7(GND_D)
DISCHARGE_GATE: Q29.G(GATE) U24.3(DOUT)
EEPROM_E0: R788.2 R790.2 U16.1(E0)
EEPROM_E1: R787.2 R791.2 U16.2(E1)
EEPROM_E2: R786.2 R792.1 U16.3(E2)
FACTORY_RST: R732.2 U10.22(GPIO4)
G1: S3.4(G1)
G2: S3.5(G2)
G3: S3.6(G3)
JTAG_TI_TCK: J13.1 R881.1 R882.1
JTAG_TI_TCK_R: R881.2 U21.B15(PC0_TCK_SWCLK)
JTAG_TI_TDI: J13.2 R474.1 R475.1
JTAG_TI_TDI_R: R474.2 U21.D14(PC2_TDI)
JTAG_TI_TDO: J13.3 R473.1
JTAG_TI_TDO_R: R473.2 U21.C14(PC3_TDO_SWO)
JTAG_TI_TMS: J13.4 R469.1 R471.1
JTAG_TI_TMS_R: R469.2 U21.C15(PC1_TMS_SWDIO)
LCD_C1M: C295.2 C297.2 J4.5
LCD_C1P: C297.1 J4.6
LCD_C2M: C296.2 J4.3
LCD_C2P: C296.1 J4.4
LCD_C3P: C295.1 J4.2
LCD_PAGE_SKP_DOWN: R915.1 SW6.6 U21.W10(PT0)
LCD_PAGE_SKP_ENTER: R916.1 SW6.2 U21.W6(PF2)
LCD_PAGE_SKP_LEFT: R914.1 SW6.3 U21.V7(PF4)
LCD_PAGE_SKP_PU: R919.2 SW6.5
LCD_PAGE_SKP_RIGHT: R918.1 SW6.4 U21.R10(PR7)
LCD_PAGE_SKP_UP: R917.1 SW6.1 U21.V4(PA4_SSI0XDAT0)
LCD_V0: C290.1 J4.7
LCD_V1: C292.1 J4.8
LCD_V2: C291.1 J4.9
LCD_V3: C293.1 J4.10
LCD_V4: C294.1 J4.11
LCD_VLCD: C298.1 J4.1
LCD_VREF: C299.1 J4.12
LED_A1_N: D6.17(A1) U21.R2(PH1)
LED_A2_N: D6.12(A2) U21.C10(PN0)
LED_B1_N: D6.16(B1) U21.R1(PH2)
LED_B2_N: D6.11(B2) U21.B11(PN1)
LED_C1_N: D6.4(C1) U21.T1(PH3)
LED_C2_N: D6.9(C2) U21.A11(PN2)
LED_D1_N: D6.2(D1) U21.R3(PH4)
LED_D2_N: D6.7(D2) U21.B10(PN3)
LED_DP1_N: D6.5(DP1) U21.V2(PH7)
LED_DP2_N: D6.10(DP2) U21.U12(PN7)
LED_E1_N: D6.1(E1) U21.T2(PH5)
LED_E2_N: D6.6(E2) U21.A10(PN4)
LED_F1_N: D6.19(F1) U21.P4(PH0)
LED_F2_N: D6.14(F2) U21.B9(PN5)
LED_G1_N: D6.20(G1) U21.U2(PH6)
LED_G2_N: D6.15(G2) U21.T12(PN6)
LED_P3V3_BT_R: D3.A R12.1
NMOS_D: Q29.D(DRAIN) Q30.D(DRAIN)
PD_EEPROM_WC: R789.1 U16.7(W\C\)
PU_25M_BMC_CLK_EN_R: OSC1.1(OE) R51.2
PWR_BTN: R78.2 U21.F18(PJ4)
PWR_BTN_R: C21.2 R78.1 R944.1 S1.3 S1.4
PWRGD_P3V3: Q13.G Q14.G(GATE) R808.1 R903.1 U12.5(PGOOD)
PWRGD_P3V3_BAT: PR38.2 PU1.8(PG)
Q21_G: Q21.G R905.1 R906.1
REV_ID_0: R920.1 R921.2 U21.G19(PL5)
REV_ID_1: R922.1 R923.2 U21.H18(PL4)
RST_BTN: R725.2 U21.C6(PB4_AIN10)
RST_BTN_R: C244.2 R725.1 R910.1 S2.3 S2.4
RST_LCD_N: J4.30 U21.E17(PJ5)
RST_N: C252.1 R730.2 U10.5(RESET)
S3_A2: Q31.G Q32.G(GATE) S3.2(A2)
S3_A3: D17.3 S3.3(A3)
SEG_SEL_1: D6.3(COM_DIG1_1) D6.18(COM_DIG1_2) R758.1
SEG_SEL_2: D6.8(COM_DIG2_1) D6.13(COM_DIG2_2) R759.1
SET_BAUD_RATE: R10.2 U10.4(GPIO7)
SET_BT_MASTER: R11.2 U10.3(GPIO6)
SET_BT_MODE: R2.2 U10.20(GPIO3)
SMB_SCL: R926.2 U16.6(SCL) U21.A17(PB2_I2C0SCL)
SMB_SCL_R: R925.2 R926.1 U15.5(SSRX-)
SMB_SDA: R927.2 U16.5(SDA) U21.B17(PB3_I2C0SDA)
SMB_SDA_R: R924.2 R927.1 U15.6(SSRX+)
SPI_BMC_LCD_CS_N: J4.19 R79.2
SPI_BMC_LCD_CS_N_R: R79.1 U21.E2(PQ1)
SPI_BMC_LCD_SCK: J4.22 R516.2
SPI_BMC_LCD_SCK_R: R516.1 U21.E3(PQ0)
SPI_BMC_LCD_SDI: J4.20 R513.2
SPI_BMC_LCD_SDI_R: R513.1 U21.H4(PQ2)
SPI_BMC_LCD_SDO: J4.21 R72.2
SPI_BMC_LCD_SDO_R: R72.1 U21.M4(PQ3)
SUPPLY_INPUT: C336.1 R941.1 U24.5(BAT)
TP_CBUS0: U5.23(CBUS0)
TP_CBUS1: U5.22(CBUS1)
TP_CBUS2: U5.13(CBUS2)
TP_CBUS3: U5.14(CBUS3)
TP_CBUS4: U5.12(CBUS4)
TP_CTS_N: U5.11(CTS_N)
TP_DCD_N: U5.10(DCD_N)
TP_DSR_N: U5.9(DSR_N)
TP_DTR_N: U5.2(DTR_N)
TP_LCD_INT_N: J4.29
TP_NC0: U5.8(NC0)
TP_NC1: U5.24(NC1)
TP_OSCI: U5.27(OSCI)
TP_OSCO: U5.28(OSCO)
TP_RI_N: U5.6(RI_N)
TP_RTS_N: U5.3(RTS_N)
TP_SPI_CLK: U10.6(SPI_CLK)
TP_SPI_CS: U10.23(SPI_CSB)
TP_SPI_MI: U10.24(SPI_MISO)
TP_SPI_MO: U10.2(SPI_MOSI)
TP_VBAT: U21.P19(VBAT)
UART_CH_SEL: C332.2 R880.2 R888.1 SW5.3 SW5.4
UART_CH_SEL_BIC: R888.2 R912.1 U21.F16(PJ3)
UART_CTS: R731.2 U10.16(UART_CTS)
UART_GATE: Q5.2(G1) Q5.5(G2) R357.2 R358.1
UART_RTS: R731.1 U10.15(UART_RTS)
UART_TI_R_RXD: R871.1 U21.J1(PK0_AIN16)
UART_TI_R_TXD: R870.1 U21.J2(PK1_AIN17)
UART_TI_RXD: CN1.3(D+) R871.2
UART_TI_TXD: CN1.2(D-) R870.2
USB2_DN: J1.2(D-) U15.2(D-)
USB2_DN_MICRO: J2.2(D-) U5.16(USBDM)
USB2_DP: J1.3(D+) U15.3(D+)
USB2_DP_MICRO: J2.3(D+) U5.15(USBDP)
VOLTAGE_SENSE: R942.2 U24.6(V-)
N17920453: R76.2 S1.1 S1.2
N17920501: R724.2 S2.1 S2.2
N18231426: R911.2 R913.1 SW5.1 SW5.2
N18364020: PL1.1 PU1.1(L1)
N18364026: PL1.2 PU1.3(L2)
N18364174: PC3.1 PU1.7(SS)
N18390536: D15.A R930.1
N18393594: C329.1 R895.2

Pads without a net: DM8 1; DM9 1; J2 4; J4 17 18; NOREF#23 1; NOREF#31 1; NOREF#32 1; TP7 1; U10 7 8 9 10 17 18 19 30 31 32 33 34 35; U21 A4 A5 A7 A8 A13 A14 A16 B2 B3 B4 B5 B6 B8 B12 B13 B14 B16 B18 C1 C2 C5 C8 C12 C18 D1 D2 D6 D7 D8 D12 D13 D19 E13 E18 F1 F2 F17 G1 G2 G15 G16 G18 H2 H3 H17 H19 J18 K1 K2 K3 K5 K15 K17 K18 K19 L2 L18 L19 M1 M2 M3 M16 M17 M18 N1 N2 N4 N5 N15 N18 N19 P2 P3 R7 R13 T6 T7 T8 T14 T18 T19 U5 U6 U8 U10 U14 U15 U18 V5 V6 V8 V9 V10 V11 V12 V13 V14 V15 V17 V18 V19 W4 W7 W9 W12 W13 W15 W16 W18 W19; U24 1

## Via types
v1: diameter 0.508, hole 0.254, TOP to BOTTOM, 308 vias
v2: diameter 0.457, hole 0.254, TOP to BOTTOM, 69 vias

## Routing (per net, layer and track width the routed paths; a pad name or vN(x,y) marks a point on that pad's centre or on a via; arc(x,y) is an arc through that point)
GND: length 161.2
  TOP w0.165: 28.65,12.85 U22.C2
  TOP w0.254: R905.2 31.85,5.33 v1(32.23,5.71) ; v1(33.15,9.4) 32.92,9.16 R865.2 C335.2 ; v1(11.08,5.74) 11.08,5.99 11.44,6.35 R943.1 ; U23.5 28.09,9.2 27.81,9.48 v1(26.82,9.48) ; v2(46.13,21.92) 46.04,21.83 U21.M8 ; U21.M9 U21.M10 U21.N10 v2(44.53,21.95) ; U21.M9 v2(45.54,21.95) ; U21.M9 U21.L9 ; U21.M9 U21.M8 ; PU1.6 20.98,12.77 v1(21.29,13.08) ; U21.W2 49.04,25.01 48.6,25.45 v2(48.6,25.81) ; U21.M8 U21.L8 U21.L9 ; v2(48.53,15.97) 48.55,15.95 49.04,15.95 U21.A2 ; U21.A19 40.44,15.85 v2(40.44,15.47) ; v2(43.65,19.18) 43.92,19.45 U21.H12 U21.H11 U21.H10 ; U21.K10 U21.K9 U21.L9 ; v2(40.56,22.95) U21.R18 U21.R17 v2(41.54,23.47) ; U21.V1 49.58,24.45 50,24.87 v1(50,25.16) ; R915.2 14.28,13.13 v1(14.35,13.06) ; v2(46.67,19.2) 46.92,18.95 U21.G5 U21.G4 ; U21.A18 v2(41.04,15.47) ; U21.B1 U21.A1 49.54,15.92 49.14,15.51 48.09,15.51 v2(48.04,15.47) ; U21.P16 v2(42.55,22.45) ; U21.F10 44.69,18.45 v2(44.53,18.29) ; U21.D18 v2(41.54,17.45) ; 28.65,12.85 28.65,12.57 v1(28.63,12.56) ; U21.W1 49.52,24.97 49.52,25.09 49.18,25.43 v2(49.18,25.53) ; v2(46.64,19.81) 47.04,20.21 U21.K6 ; U21.B19 v2(40.54,16.94) ; U21.J11 U21.J12 43.55,19.95 v2(43.54,19.94) U21.K13 ; v2(43.14,19.51) 43.04,19.6 U21.K14 ; v1(25.38,1.91) 25.64,1.65 C301.2
  TOP w0.381: v1(34.88,20.32) 33.87,19.3 C65.2 ; C289.2 52.44,7.85 v1(52.54,7.94) ; v1(26.14,19.08) 26.12,19.09 25.18,19.09 R896.2 ; R918.2 15.35,10.08 15.35,7.92 R942.1
  TOP w0.457: OSC1.2 35.24,16.62 v1(35.75,17.14) ; v1(32.69,7.1) 32.76,7.1 32.9,7.24 R864.2 ; v1(47.68,8.48) 44.66,8.48 43.91,7.73 C294.2 C299.2 ; R900.1 56.45,19.98 v1(55.76,20.68) ; C255.2 42.03,3.3 v1(41.39,3.94) 41.39,4.31 41.12,4.58 C254.2 ; SW6.G4 7.3,8.35 6.59,9.07 6.56,9.07 6.51,9.12 v1(6.52,9.12) ; v1(34.88,20.32) R921.1 R923.1 ; PC3.2 v1(21.77,15.72) ; v1(59.63,1.41) 59.9,1.68 R790.1 ; v1(42.53,11.98) 42.54,11.96 C293.2 C291.2 C292.2 C290.2 C298.2 ; v1(14.35,13.06) 14.44,12.97 14.44,10.98 R918.2 ; v1(4.95,11.95) SW6.G3 ; PC2.2 15.98,13.86 16.19,14.07 PC1.2 16.98,14.35 v1(17.48,14.86) ; S3.7 24.05,1.05 v1(24.34,0.76) ; v1(58.96,1.42) 58.89,1.5 R791.1 ; C327.2 35.52,12.98 35.77,12.73 v1(35.77,12.7) ; R808.2 38.97,8.15 40.14,9.32 v1(40.39,9.32) 40.39,8.89 41.15,8.13 C300.2 41.15,7.41 41.12,7.39 R742.2 ; v1(52.54,7.94) 52.59,7.89 53.14,7.89 R789.2 ; S3.1 v1(18.04,4.45) ; v1(10.09,13.92) 10.09,14.74 SW6.G1 ; v1(10.77,12.09) 11.17,12.09 SW6.G2 ; C244.1 v1(30.15,31.23) ; C330.2 v1(26.14,19.08) ; U16.4 60.37,9.74 60.64,10.01 v1(61.73,10.01) ; R792.2 59.27,13.74 59.28,13.73 v1(59.43,13.73) ; R910.2 v1(28.04,31.23)
  BOTTOM w0.254: C320.2 47.12,16.47 47.23,16.36 47.23,15.56 v1(47.23,15.55) ; C279.2 40.32,21.21 v2(40.14,21.39) ; v2(41.54,23.47) 41.21,23.14 C317.2 ; v1(40.39,9.32) 40.7,9.32 41.1,8.92 J4.13 ; v1(57.51,36.25) 57.84,36.58 C21.1 ; v2(40.01,19.43) 40.22,19.23 C322.2 ; J4.28 33.6,7.35 33.41,7.16 32.75,7.16 v1(32.69,7.1) ; C258.2 44.44,18.38 v2(44.53,18.29) 44.66,18.16 C273.2 ; U5.26 44.05,33.17 v1(43.98,33.11) 43.98,32.77 44.23,32.52 U5.25 ; C302.2 29.88,2.54 v1(30.46,1.96) 30.03,1.52 C308.2
  BOTTOM w0.381: C331.2 25.01,8.8 25.69,9.48 v1(26.82,9.48) ; U5.18 43.96,27.97 43.72,28.21 C241.1 ; U5.21 44.15,29.92 43.83,30.25 C243.1 ; U5.7 53.46,30.57 v1(53.73,30.3) ; v1(29.52,9.7) 30.33,9.7 R933.2 ; R358.2 40.16,29.39 39.68,29.87 J1.G1 ; Q26.S v1(23.14,19.8) ; v1(22.56,4.78) 22.58,4.78 R929.2 ; C4.1 16.63,18.35 v1(16.26,17.98) ; v1(48.37,6.65) 48.75,6.27 J4.G1
  BOTTOM w0.457: v1(43.7,37.47) R912.2 R913.2 ; v1(42.78,30.41) 43.25,30.41 C243.1 ; C329.2 v1(26.43,14.1) 26.43,14.64 R893.2 ; C259.2 39.15,18.41 v1(38.79,18.06) ; U10.1 15.22,31.11 16.09,30.25 v1(16.09,29.9) ; v1(17.28,6.35) 17.81,6.88 BT1.G2 ; U15.4 56.09,21 v1(55.76,20.68) ; R944.2 60.82,31.78 v1(60.92,31.78) ; v1(29.52,9.7) 29.15,9.7 C334.2 ; BT1.G1 12.06,5.94 11.29,5.94 v1(11.08,5.74) ; C241.1 42.75,28.21 v1(42.73,28.19) ; C333.2 22.06,5.28 v1(22.56,4.78) ; CN1.5 17.76,33.88 17.75,33.88 v1(17.75,33.88) ; U10.29 11.25,14.09 v1(11.11,13.94) ; v1(15.27,34.8) 15.26,34.81 U10.G1 ; U10.G2 3.37,34.81 v1(3.77,34.42) ; J5.1 55.46,7.34 55.46,8.21 55.73,8.48 56.76,8.48 ; v1(2.12,12.95) 2.25,13.09 U10.G4 ; v1(17.28,34.39) 17.41,34.53 17.75,34.53 17.76,34.53 CN1.4 ; v1(13.81,17.91) U10.12 14.85,17.31 14.52,16.98 14.52,16.58 U10.G3 ; C323.2 v1(37.93,17.37) ; C332.1 v1(39.94,36.45) ; C252.2 v1(19.01,26.29) ; v1(28.02,12.37) 27.95,12.37 27.88,12.3 R894.2 ; v1(4.35,12.57) 4.35,12.75 4.95,13.35 U10.28 ; C242.1 54.57,31.22 v1(54.57,31.01)
  vias: v1(0.77,31.93) v1(0.77,14.5) v1(0.77,7.92) v1(0.77,5.31) v1(2.52,22.17) v1(2.65,24) v1(2.85,0.76) v1(6.02,9.54) v1(16.42,36.2) v1(19.36,12.32) v1(19.69,12.93) v1(19.87,39.22) v1(23.2,11.76) v1(23.68,39.22) v1(23.83,11.76) v1(25.64,40.36) v1(30.36,40.36) v1(31.66,17.09) v1(32.22,6.48) v1(34.78,40.36) v1(36.48,6.71) v1(36.48,4.6) v1(37.7,6.73) v1(37.7,4.6) v1(38.77,40.34) v1(58.05,39.22) v1(61.73,33.91) v1(61.73,30.86) v1(61.73,25.3) v1(61.73,21.89) v1(61.73,13.54) v1(61.73,6.99) v1(61.73,2.29) v2(46.67,22.48) v2(46.72,21.87) v2(49.33,28.98) v2(50.66,28.96)
P3V3_ADJ: length 2.8
  TOP w0.165: U12.4 39.18,6.16 39.51,5.84 R743.2 R742.1
P3V3_BAT: length 41.7
  TOP w0.381: Q13.D v1(49.73,2.68)
  TOP w0.457: 21.95,10.52 21.9,10.57 ; v1(21.07,6.11) 21.59,6.11 22.06,6.57 22.06,10.41 22,10.46
  BOTTOM w0.381: v1(49.73,2.68) 46.51,2.68 46.03,3.15 44.33,3.15 43.54,2.36 36.41,2.36 34.5,4.27 33.03,4.27 32.29,3.53 30.64,3.53 27.54,6.63 24.19,6.63 23.88,6.32 23.88,4.68 23.39,4.18 21.61,4.18 21.07,4.71 v1(21.07,6.11)
P3V3_BAT_EN: length 24.3
  TOP w0.165: PU1.11 18.66,12.77 18.85,12.57 18.85,12.05 18.69,11.89 18.5,11.89 v1(17.88,11.26) ; v1(25.43,12.55) 25.43,10.82 25.76,10.5 R907.2 26.4,8.99 27.4,8.99 U23.6
  BOTTOM w0.165: v1(17.88,11.26) 19.76,11.26 20.28,11.79 20.81,11.79 21.57,12.55 v1(25.43,12.55) 25.43,15.39 25.89,15.85 25.89,16.81 26.53,17.45 Q32.D
P3V3_BIC: length 95.7
  TOP w0.203: v2(42.6,21.44) 42.55,21.44 U21.N16 ; v2(42.14,23.44) 42.14,23.05 U21.P17
  TOP w0.254: v1(43.87,22.07) 44.04,21.9 U21.M12 ; U21.J10 U21.J9 U21.J8 v2(46.04,19.38) 46.12,19.3 46.12,18.86 v2(46.19,18.8) ; U21.G10 v2(44.56,18.95) ; v2(45.54,18.77) U21.H9 ; U21.P10 44.67,22.45 v1(44.52,22.59) ; U21.L11 U21.K11 U21.K12 U21.L12 ; U21.L11 U21.L10 ; U21.L11 U21.M11 U21.M12 ; U21.L11 U21.L12 ; U21.L12 U21.M12 ; U21.L12 v1(43.31,20.95) ; U21.M12 43.51,21.45 v1(43.34,21.62) ; R786.1 57.38,11.08 58.3,10.16 58.3,5.26 57.23,4.19 57.23,3.43 57.63,3.03 R787.1 ; v2(48.54,18.95) U21.F3 U21.F4 48.04,18.29 v2(47.79,18.03) ; R919.1 10.59,5.44 12.32,3.72 12.32,3.67 v1(12.52,3.46) ; v2(47.48,20.92) 47.45,20.9 v2(46.88,20.9) 46.81,20.9 46.54,20.62 46.54,20.45 U21.K7 U21.K8
  TOP w0.381: C254.1 40.19,4.83 v1(39.68,4.32) ; D17.2 25.9,6.29 v1(26.37,5.81) ; v1(52.2,5.18) 52.48,5.46 53.07,5.46 53.24,5.63 C289.1 54.63,6.05 U16.8 ; R743.1 41.36,5.84 42.1,5.11 v1(42.1,4.42) ; R787.1 57.87,2.21 57.28,1.63 v1(56.75,1.63) ; R788.1 v1(60.92,2.36) ; Q14.S v1(43.31,3.11)
  TOP w0.457: v1(34.93,19.41) 35.03,19.3 R920.2 ; v1(51.8,14.56) 53.5,14.56 R925.1 R924.1 ; R922.2 v1(34.75,21.47) ; v1(36.53,12.7) 36.53,12.95 36.54,12.96 36.54,13.71 v1(36.53,13.72) 36.53,13.84 36.54,13.85 36.54,14.6 36.53,14.61 v1(36.53,14.73) 36.66,14.86 36.67,14.86 36.92,15.11 37.15,15.11 37.6,15.56 37.6,16.21 37.15,16.67 36.38,16.67 35.47,15.76 35.05,15.76 34.5,15.21 34.5,15.16 34.48,15.14 v1(34.48,15.06) 34.3,15.24 R51.1 ; v1(39.71,7.21) 39.71,7.69 39.89,7.87 C300.1 ; v1(51.34,15.85) 51.34,16.31 54.97,19.94 54.97,20.88 56.37,22.28 56.37,27.46 v1(55.89,27.94) ; OSC1.4 33.02,19.25 C65.1 32.96,19.51 v1(34.32,20.87)
  TOP w0.508: D13.A 1.66,1.72 v1(2.12,1.27)
  BOTTOM w0.254: C317.1 42.01,23.31 v2(42.14,23.44) ; v1(2.12,1.27) 2.32,1.47 3.05,1.47 4.27,0.97 8.47,0.97 10.96,3.46 v1(12.52,3.46) ; R76.1 58.26,38.37 v1(58.05,38.58)
  BOTTOM w0.381: v1(39.84,35.56) 39.96,35.43 R880.1 ; R936.1 34.02,14.61 v1(34.48,15.06)
  BOTTOM w0.457: R875.1 38.25,20.61 v1(38.29,20.57) ; R475.2 v1(36.53,13.72) ; v1(46.01,38.79) 45.63,39.17 44.87,39.17 44.41,38.71 R724.1 ; R911.1 39.1,38.48 v1(39,38.58) ; v1(51.34,15.85) 51.34,15.02 v1(51.8,14.56) ; v1(36.53,14.73) R471.2 ; v1(36.53,12.7) R882.2
  vias: v1(30.59,20.37) v1(33.95,9.32) v1(34.59,9.3) v1(34.75,7.21) v1(35.38,7.21) v1(38.59,9.42) v1(38.82,3.68) v1(38.82,3.03) v1(39.47,3.69) v1(39.47,3.04) v1(39.71,6.57)
P3V3_BT: length 50.3
  TOP w0.508: R12.2 3.8,2.43 v1(3.39,2.03) ; v1(18.7,4.45) 18.7,4.95 17.99,5.66 16.31,5.66 15.65,5 14.41,5 13.9,4.5 v1(13.44,4.5) ; v1(1.74,10.82) 1.74,11.03 R2.1 R732.1
  BOTTOM w0.508: U10.11 17.12,19.11 C4.2 17.18,19.18 17.18,21.8 17.19,21.8 21.8,26.42 21.8,28.42 20.96,29.26 18.47,29.26 R11.1 ; R11.1 18.39,29.85 v1(18.22,30.02) ; R11.1 R10.1 R730.1 ; v1(27.69,2.24) 26.31,2.24 23.82,3.27 19.88,3.27 v1(18.7,4.45) ; v1(13.44,4.5) 13.22,4.27 10.94,4.27 8.35,1.68 5.51,1.68 5.16,2.03 v1(3.39,2.03)
  vias: v1(27.69,1.57)
P3V3_BT_ON: length 25.3
  TOP w0.165: v1(23.83,11.05) 22.99,10.21 22.99,9.47 24.49,5.86 25.13,5.22 27.78,5.22 28.6,4.4 Q21.S
  BOTTOM w0.165: v1(23.83,11.05) 24.84,12.06 25.73,12.06 26.09,12.42 26.09,13.26 25.87,13.49 25.87,15.09 26.3,15.52 26.3,16.33 26.88,16.92 28.25,16.92 28.74,16.42 Q31.D
P3V3_EN: length 2.6
  TOP w0.165: U12.6 34.99,6.66 34.55,6.22 R762.2 R864.1
P3V3_SW: length 66.9
  TOP w0.254: R360.1 44.52,31.24 44.77,30.99 48.04,30.99 48.42,31.37 50.83,31.37 51.75,30.99 52.54,30.2 52.54,28.37 54.84,26.07 54.84,22.95 53.98,22.1 v1(53.02,22.1)
  TOP w0.508: v1(50.76,8.76) 50.37,8.37 48.52,3.91 Q13.S 46.78,4.06 Q14.D ; R360.1 44.36,31.67 40.9,31.67 v1(40.65,31.42)
  BOTTOM w0.508: v1(25.66,34.03) 37,34.03 38.91,32.11 R359.1 40.34,31.72 v1(40.65,31.42) ; v1(50.76,8.76) 54.72,12.73 54.72,16.84 53.73,17.83 53.73,21.39 v1(53.02,22.1) ; Q31.S 33.9,18.66 33.28,19.28 v1(31.3,19.28)
P3V3_VOUT: length 16.5
  TOP w0.457: v1(46.64,37.01) 46.74,37.11 48.52,37.11 52.38,35.51 v1(52.71,35.18)
  BOTTOM w0.381: U5.17 43.5,27.32 C241.2 ; C242.2 54.07,32.52 U5.4
  BOTTOM w0.457: C242.2 54.44,32.66 54.44,34.72 53.98,35.18 v1(52.71,35.18)
  BOTTOM w0.508: C241.2 42.56,27.41 42.05,27.92 v1(42.05,28.19)
P5V_MB: length 13.3
  TOP w0.254: v1(45.17,2.44) 45.17,3.61 44.69,4.09 43.34,4.09 42.63,4.8 R903.2
  TOP w0.457: D16.A 34.65,13.97 35.52,14.83 C327.1 35.61,14.96 36.56,15.91 36.64,15.91 v1(36.69,15.95) ; v1(55.53,17.68) 56.14,18.29 R901.2
  TOP w0.508: R758.2 7.97,17.49 v1(8.16,17.3) ; v1(12.28,16.68) R759.2
  BOTTOM w0.508: v1(20.12,36.93) 19.67,36.48 CN1.1
  vias: v1(25.28,27.25) v1(25.31,26.49) v1(25.31,25.74) v1(33.47,3.38) v1(33.45,2.74) v1(34.13,3.38) v1(34.17,2.74) v1(55.33,1.47) v1(55.53,14.48) v1(55.53,13.84) v1(55.53,13.21) v1(55.94,1.65) v1(56.95,10.46) v1(56.95,9.8) v1(56.97,9.15)
P5V_MB_LCD: length 3.5
  TOP w0.457: R757.1 56.82,2.88 v1(56.75,2.95)
  BOTTOM w0.457: v1(56.75,2.95) 56.75,3 56.05,3.71 J5.2
P5V_USB: length 1.5
  TOP w0.381: v1(31.43,7.19) 31.43,6.63 31.15,6.35 R906.2
  vias: v1(41.18,28.19)
VBAT: length 65.7
  TOP w0.254: 18.74,14.33 PU1.10 ; U23.2 28.09,6.73 ; 17.88,12.27 PU1.12
  TOP w0.381: C330.1 27.62,18.82 v1(27.39,19.05)
  TOP w0.457: v1(18.64,15.52) 18.74,15.42 18.74,14.33 ; v1(18.64,15.52) 18.83,15.72 PR38.1 ; v1(18.64,15.52) 18.63,15.52 16.21,15.52 15.53,14.83 ; v1(16.04,8.01) 16.04,10.34 15.37,11 15.37,12.73 PC2.1 16.51,13.06 PC1.1 17.55,12.6 17.88,12.27
  TOP w0.508: PC2.1 15.41,13.06 14.94,13.53 14.94,14.25 15.53,14.83
  BOTTOM w0.254: BT1.1 15.35,3.71 14.69,3.05 13.19,3.05 12.94,2.79 R941.2
  BOTTOM w0.381: R902.1 22.94,15.62 22.61,15.29 v1(22.61,14.78) ; R934.1 27.45,7.79 v1(26.53,7.79) ; v1(27.39,19.05) 27.39,20.57 R930.2 ; v1(29.24,23.95) 21.93,23.95 19.29,21.31 19.29,17.58 18.64,16.93 v1(18.64,15.52)
  BOTTOM w0.406: v1(26.53,7.79) 26.53,7.97 26.02,8.48 C331.1
  BOTTOM w0.457: BT1.1 15.35,4.51 14.69,5.17 14.69,7.59 15.1,8.01 v1(16.04,8.01) ; v1(22.61,14.78) 23.15,14.78 24.84,16.48 R935.1
  BOTTOM w0.508: C331.1 25.76,8.44 25.76,8.03 25.51,7.77 22.87,7.77 22.62,8.02 R928.1 21.62,8.46 16.49,8.46 v1(16.04,8.01)
VBAT_3.2V_TRIGGER: length 5
  TOP w0.165: U23.4 28.59,9.01 28.75,9.17 29.5,9.17 C335.1 R865.1 31.33,7.8 30.89,7.37 R898.2
VBAT_3.3V_LOW_LED: length 4.3
  TOP w0.165: U23.3 28.59,7.85 28.75,8.01 29.05,8.01 v1(29.49,8.45)
  BOTTOM w0.165: R933.1 29.93,8.9 v1(29.49,8.45) 29.44,8.5 C334.1 28.38,8.86 R934.2
VBAT_LOW_LED: length 14.5
  TOP w0.165: U23.1 27.59,7.99 27.41,8.16 27.22,8.16 v1(26.89,8.49) ; v1(28.2,9.88) 27.9,10.19 27.54,10.19 25.94,11.79 25.94,12.75 25.2,13.49 25.2,14.68 v1(23.66,16.23)
  BOTTOM w0.165: v1(28.2,9.88) 27.95,9.88 26.89,8.81 v1(26.89,8.49) ; v1(23.66,16.23) 23.71,16.23 24.04,16.57 R935.2 24.04,17.25 25.04,18.25 Q26.G
VBAT_LOW_LED_N: length 29.7
  TOP w0.165: v1(8.36,6.48) 8.82,6.02 8.82,2.54 D15.C
  BOTTOM w0.165: Q26.D 24.09,18.16 23.6,17.68 23.17,17.68 22.94,17.45 R902.2 22.4,17.06 21.27,15.93 21.27,14.68 20.25,13.67 20.25,12.47 19.59,11.81 15.39,11.81 14.46,10.88 11.81,10.88 9.5,8.58 9.5,7.62 v1(8.36,6.48)
VBAT_SCALED: length 34.4
  TOP w0.165: U21.B7 46.54,16.41 46.89,16.06 46.89,15.83 46.4,15.34 45.57,15.34 45.55,15.32 v2(45.49,15.32)
  BOTTOM w0.165: R929.1 C333.1 R928.2 23.95,7.22 23.99,7.19 29.8,7.19 30.95,8.33 30.95,10.42 32.17,11.64 33.17,11.64 33.76,11.05 38.13,11.05 38.44,10.74 39.71,10.74 39.91,10.54 41.54,10.54 42.46,11.47 42.92,11.47 43.49,12.04 43.76,12.04 45.27,13.55 45.27,14.84 45.49,15.06 v2(45.49,15.32)
VDDC_OUTPUT: length 9.9
  TOP w0.254: U21.H16 v2(42.53,19.45) ; v2(44.53,17.65) 44.75,17.65 U21.E10
  BOTTOM w0.457: v2(44.53,17.65) 44.46,17.58 C258.1 43.64,17.58 43.19,18.03 43.19,18.54 42.53,19.2 v2(42.53,19.45) 42.31,19.23 C322.1 41.71,19.74 41.36,20.09 39.44,20.09 C259.1 38.1,19.81 C323.1
BMC_HARTBEAT_LED_R: length 59.4
  TOP w0.165: v1(6.59,6.88) 6.41,6.71 6.41,4.22 6.03,3.83 6.03,2.46 5.7,2.13 5.1,2.13 4.06,3.17 3.11,3.17 R512.1 ; U21.T13 v2(43.54,23.97)
  BOTTOM w0.165: v2(43.54,23.97) 43.17,23.97 42.46,24.68 40.66,24.68 38.57,22.58 34.47,22.58 33.37,23.68 31.64,23.68 29.89,21.94 22.39,21.94 21.32,20.86 21.32,17.73 19.97,16.38 19.97,15.06 18.02,13.11 15.12,13.11 14,11.99 11.35,11.99 10.92,11.56 10.61,11.56 10.18,11.99 9.15,11.99 8.39,11.23 8.39,8.29 7.35,7.25 6.95,7.25 v1(6.59,6.88)
BMC_HEARTBEAT_LED: length 1.6
  TOP w0.165: D13.C 2.09,2.67 R512.2
BMC_RST_N: length 3.3
  TOP w0.165: v2(41.52,21.93) 41.04,22.41 U21.P18
  BOTTOM w0.165: R875.2 39.69,21.6 39.94,21.85 41.44,21.85 v2(41.52,21.93)
BMC_UART_R_RX: length 17.7
  TOP w0.165: v1(45.09,35.79) 45.35,35.53 48.2,35.53 49.46,35.01 50,34.48 v1(50,34.34) ; v2(48.01,25.83) 48.01,25.53 48.54,25 U21.W3
  BOTTOM w0.165: v1(45.09,35.79) 45.09,36.12 44.76,36.45 R54.2 ; v1(50,34.34) 48.63,32.98 48.63,26.58 48.01,25.95 v2(48.01,25.83)
BMC_UART_R_TX: length 16.7
  TOP w0.165: v2(48.06,23.96) U21.V3 ; v1(44.51,35.21) 44.56,35.21 44.7,35.06 48.1,35.06 v1(48.14,35.03)
  BOTTOM w0.165: v2(48.06,23.96) 48.06,25.12 47.54,25.64 47.54,26.15 48.14,26.75 v1(48.14,35.03) ; R873.2 44.28,35.43 v1(44.51,35.21)
BMC_UART_RX: length 134.2
  TOP w0.165: v1(42.2,36.27) 42.81,36.88 45.75,36.88 46.16,36.47 48.41,36.47 49.97,35.83 51.21,34.59 51.21,33.1 51.57,32.74 54.39,32.74 54.54,32.89 57.13,32.89 58.43,31.6 58.43,29.93 57.49,27.66 57.49,22.99 57.55,22.85 57.77,22.63 60.13,22.63 61.31,21.45 61.31,16.87 60.92,16.47 60.92,14.86 60.33,14.27 v1(59.85,14.27) 59.72,14.27 59.52,14.48 56.94,14.48 56.52,14.05 56.52,12.79 55.51,11.78 55.51,11.15 56.07,10.59 56.07,5.19 55.23,4.35 55.23,3.25 52.57,0.59 25.27,0.59 24.06,1.8 22.54,1.8 21.24,3.1 17.25,3.1 16.12,1.97 14.94,1.97 14.14,1.17 11.9,1.17 11.39,1.68 10.4,1.68 9.86,2.21 9.86,3.2 9.3,3.76 9.3,6.38 8.69,6.99 7.18,6.99 3.86,10.3 2.79,10.3 2.22,9.73 1.26,9.73 0.62,10.36 0.62,13.22 R1.1
  BOTTOM w0.165: U15.9 58.86,14 59.14,14.27 v1(59.85,14.27) ; Q5.6 41.75,31.5 R359.2 40.34,33.5 40.72,33.88 41.46,33.88 41.94,34.37 41.94,36.02 v1(42.2,36.27) 42.4,36.47 42.95,36.47 R54.1
BMC_UART_RX_FT232: length 12.5
  TOP w0.165: v1(42.63,34.04) 42.8,34.21 43.13,34.21 43.49,34.56 49.24,34.56 49.49,34.32 49.49,33.96 v1(50.01,33.44)
  BOTTOM w0.165: v1(50.01,33.44) 51.04,34.47 U5.1 ; v1(42.63,34.04) 42.3,34.04 41.75,33.49 Q5.1
BMC_UART_RX_R: length 5.8
  TOP w0.165: R1.2 1.4,14.95 1.4,17.02 1.94,17.55 v1(2.29,17.55)
  BOTTOM w0.165: U10.14 2.08,19.11 2.24,18.95 2.24,17.7 2.29,17.65 v1(2.29,17.55)
BMC_UART_TX: length 123.4
  TOP w0.165: v1(42.46,34.89) 43.95,36.37 45.55,36.37 45.92,36 48.32,36 49.73,35.41 50.74,34.39 50.74,32.9 51.38,32.27 52.57,32.27 57.02,27.83 57.02,22.87 57.23,22.36 57.44,22.15 59.93,22.15 60.84,21.23 60.84,17.54 v1(60.2,16.9) 60.12,16.81 58.62,16.81 56.05,14.25 56.05,12.99 55.04,11.98 55.04,10.83 55.59,10.28 55.59,5.38 54.72,4.51 54.72,3.43 52.35,1.06 25.49,1.06 24.21,2.34 22.69,2.34 21.46,3.57 16.99,3.57 15.86,2.44 14.74,2.44 13.95,1.65 12.78,1.65 12.15,2.29 10.83,2.29 10.37,2.74 10.37,3.51 9.78,4.09 9.78,6.63 8.95,7.47 7.36,7.47 4.06,10.77 2.57,10.77 2.09,10.29 1.4,10.29 1.09,10.6 1.09,12.67 R13.1
  BOTTOM w0.165: U15.8 58.5,16 59.4,16.9 v1(60.2,16.9) ; v1(42.46,34.89) 42.98,35.4 R873.1 43.25,35.16 Q5.3
BMC_UART_TX_FT232: length 11.2
  TOP w0.165: v1(43.24,32.36) 44.91,32.36 45.32,31.96 R360.2 46.07,32.28 49.61,32.28 v1(49.61,32.28)
  BOTTOM w0.165: v1(43.24,32.36) 43.25,32.35 Q5.4 ; U5.5 50.02,31.87 v1(49.61,32.28)
BMC_UART_TX_R: length 3.6
  TOP w0.165: R13.2 1.91,15.46 v1(1.91,16.71)
  BOTTOM w0.165: U10.13 1.25,17.5 1.76,16.99 1.76,16.87 v1(1.91,16.71)
BQ25101_CHG_N: length 26.7
  TOP w0.165: v1(31.7,15.77) 31.7,16.03 31.15,16.57 31.15,17.91 32.43,19.19 32.43,20.13 35.64,23.34 38.41,23.34 v1(39.52,22.24) ; v2(41.81,24) 42.04,24.23 U21.V16 ; v1(27.64,13.08) 27.75,13.19 U22.C1
  BOTTOM w0.165: v1(31.7,15.77) 31.89,15.77 32.58,15.08 R936.2 32.48,14.5 30.34,14.5 29.68,13.84 29.68,13.41 29.35,13.08 v1(27.64,13.08) 27.62,13.1 R894.1 ; v1(39.52,22.24) 39.98,22.7 39.98,22.97 41,24 v2(41.81,24)
BQ25101_IN: length 4.6
  TOP w0.508: D16.C 32.67,13.97 31.97,14.67 31.97,14.89 v1(31.82,15.04)
  BOTTOM w0.508: v1(28.95,14.9) 29.09,15.04 v1(31.82,15.04)
BQ25101_ISET: length 4.6
  TOP w0.165: v1(29.17,13.59) U22.B2
  BOTTOM w0.165: v1(29.17,13.59) 29.17,13.97 28.46,14.68 28.46,15.73 28.24,15.94 R895.1 R893.1
BQ25101_TS: length 6.1
  TOP w0.165: U22.B1 27.84,13.59 27.52,13.91 27.52,14.26 26.91,14.87 26.91,15.92 24.93,17.9 R896.1
BT_STATUS_N: length 28.5
  TOP w0.165: v1(3.3,9.8) 3.3,5.04 D3.C
  BOTTOM w0.165: v1(3.3,9.8) 3.3,10.65 2.9,11.06 2.9,14.51 3.46,15.08 3.46,15.73 3.74,16 3.89,16 4.09,16.19 4.09,17.04 4.58,17.54 4.58,25.48 2.56,27.5 2.13,27.5 2.12,27.51 U10.21
CELL_NEGATIVE: length 20.9
  TOP w0.102: Q29.S 12.78,8 v1(13.27,8.48)
  TOP w0.165: R943.2 11.72,5.57 12.2,6.05 12.2,7.09 11.9,7.39 11.9,9.19 12.33,9.63 14.18,9.63 14.66,9.14 v1(14.66,8.51) ; R943.2 11.72,4.96 13.01,3.66 v1(13.01,2.29) ; R943.2 12.82,5.55 U24.4
  BOTTOM w0.165: v1(13.27,8.48) 13.29,8.51 v1(14.66,8.51) ; C336.2 12.5,1.78 v1(13.01,2.29) 13.36,2.64 15.8,2.64 16.6,3.44 BT1.2
CHARGE_GATE: length 1.3
  TOP w0.102: U24.2 13.32,7.16 13.73,7.57 Q30.G
CLK_25M_MINIBMC_CLKIN: length 2
  TOP w0.165: R44.1 35.74,17.92 OSC1.3
CLK_25M_MINIBMC_CLKIN_R: length 4.6
  TOP w0.165: R44.2 36.92,18.57 39.02,18.57 39.64,17.95 U21.E19
